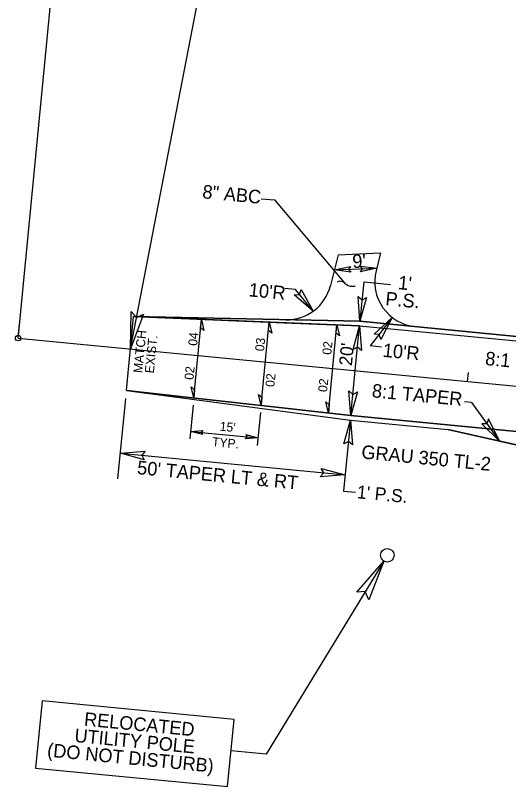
# Model space of a CAD drawing. Extents: x 2061030 to 2061632, y 912568 to 912882.
# Drawn here: x 2061029.7 to 2061138.9, y 912624.1 to 912794.9 of the extents above; entities that cross this region are included whole.
import ezdxf

# ---------------------------------------------------------------- set-up
doc = ezdxf.new("R2010")
doc.units = 0
for name, color, linetype in [('Prop Dimension', 7, 'Continuous'), ('Prop Dimension Text', 7, 'Continuous'), ('Prop EOT', 7, 'Continuous'), ('Prop Guardrail Anchor Unit CELL', 7, 'Continuous'), ('Prop Horizontal Alignment', 7, 'Continuous'), ('Prop Horizontal Alignment Station Label', 7, 'Continuous'), ('Prop Horizontal Alignment Tick Large', 7, 'Continuous'), ('Prop Horizontal Alignment Tick Small', 7, 'Continuous'), ('Prop Lane Lines', 7, 'Continuous'), ('Prop Paved Shoulder', 7, 'Continuous'), ('Prop Shade Light', 7, 'Continuous'), ('Prop Shade Medium', 7, 'Continuous'), ('Prop Superelevation  Arrow CELL', 7, 'Continuous'), ('Prop Superelevation Label', 7, 'Continuous'), ('Prop Terminator CELL', 7, 'Continuous')]:
    doc.layers.add(name, color=color, linetype=linetype)

msp = doc.modelspace()

# ---------------------------------------------------------------- linework, layer by layer
at = {"layer": 'Prop Dimension'}
for p, q in [((2061055.22, 912721.01), (2061080.91, 912854.17)), ((2061084.16, 912754.29), (2061087.18, 912754.01)), ((2061102.92, 912735.37), (2061087.18, 912754.01)), ((2061100.37, 912738.51), (2061109.74, 912738.9)), ((2061091.78, 912734.16), (2061089.43, 912734.38)), ((2061106.88, 912735.86), (2061106.04, 912727.15)), ((2061106.88, 912735.86), (2061112.83, 912735.28)), ((2061095.64, 912729.36), (2061091.78, 912734.16)), ((2061113.19, 912728), (2061108.32, 912721.68)), ((2061104.02, 912706.25), (2061105.95, 912726.15)), ((2061110.83, 912721.44), (2061108.32, 912721.68)), ((2061052.43, 912692.24), (2061054.15, 912710.02)), ((2061130.7, 912709.18), (2061129.21, 912709.33)), ((2061130.7, 912709.18), (2061136.94, 912700.6)), ((2061103.93, 912705.25), (2061102.41, 912689.55)), ((2061052.98, 912697.92), (2061102.75, 912693.11)), ((2061102.41, 912689.55), (2061105.07, 912689.29))]:
    msp.add_line(p, q, dxfattribs=at)
msp.add_open_spline([(2061104.97, 912734.86), (2061103.28, 912734.69), (2061103.11, 912735.58), (2061101.49, 912736.24), (2061100.98, 912735.82)], degree=3, dxfattribs=at)
at = {"layer": 'Prop Dimension Text'}
for p, q in [((2061111.3, 912674.05), (2061085.29, 912631.24)), ((2061085.29, 912631.24), (2061077.48, 912632))]:
    msp.add_line(p, q, dxfattribs=at)
msp.add_lwpolyline([(2061034.19, 912628.21), (2061076.72, 912624.1), (2061078.15, 912638.95), (2061035.63, 912643.06)], close=True, dxfattribs=at)
msp.add_circle((2061112.08, 912675.33), 1.5, dxfattribs=at)
at = {"layer": 'Prop EOT'}
for p, q in [((2061054.33, 912711.84), (2061055.91, 912728.18)), ((2061055.91, 912728.18), (2061089.24, 912726.83)), ((2061105.95, 912726.15), (2061055.91, 912728.18)), ((2061105.95, 912726.15), (2061429.44, 912694.88)), ((2061054.33, 912711.84), (2061104.02, 912706.25)), ((2061104.02, 912706.25), (2061477.28, 912670.17))]:
    msp.add_line(p, q, dxfattribs=at)
at = {"layer": 'Prop Horizontal Alignment'}
msp.add_line((2061030.33, 912723.42), (2061621.2, 912666.3), dxfattribs=at)
at = {"layer": 'Prop Horizontal Alignment Station Label'}
msp.add_line((2061030.39, 912724.01), (2061043.47, 912859.35), dxfattribs=at)
msp.add_circle((2061030.33, 912723.42), 0.6, dxfattribs=at)
at = {"layer": 'Prop Horizontal Alignment Tick Large'}
msp.add_line((2061030.33, 912723.42), (2061030.64, 912726.6), dxfattribs=at)
at = {"layer": 'Prop Horizontal Alignment Tick Small'}
msp.add_line((2061129.87, 912713.8), (2061130.06, 912715.79), dxfattribs=at)
at = {"layer": 'Prop Lane Lines'}
msp.add_line((2061089.24, 912726.83), (2061105.95, 912726.15), dxfattribs=at)
at = {"layer": 'Prop Paved Shoulder'}
for p, q in [((2061101.2, 912741.84), (2061099.51, 912735.06)), ((2061101.2, 912741.84), (2061110.59, 912742.27)), ((2061110.59, 912742.27), (2061109.6, 912738.34)), ((2061055.91, 912728.18), (2061106.04, 912727.15)), ((2061106.04, 912727.15), (2061165.24, 912721.43)), ((2061054.33, 912711.84), (2061103.93, 912705.25)), ((2061103.93, 912705.25), (2061125.49, 912703.17)), ((2061148.44, 912698.02), (2061125.49, 912703.17))]:
    msp.add_line(p, q, dxfattribs=at)
for centre, start, end in [((2061119.3, 912735.91), 165.9729, 264.4787), ((2061089.81, 912737.48), 268.8252, 345.9729)]:
    msp.add_arc(centre, 10, start, end, dxfattribs=at)
at = {"layer": 'Prop Shade Light'}
msp.add_lwpolyline([(2061034.19, 912628.21), (2061076.72, 912624.1), (2061078.15, 912638.95), (2061035.63, 912643.06)], close=True, dxfattribs=at)
at = {"layer": 'Prop Shade Medium'}
for p, q in [((2061106.04, 912727.15), (2061055.91, 912728.18)), ((2061055.91, 912728.18), (2061105.95, 912726.15)), ((2061105.95, 912726.15), (2061229.25, 912714.23)), ((2061165.24, 912721.43), (2061106.04, 912727.15)), ((2061104.02, 912706.25), (2061054.33, 912711.84)), ((2061054.33, 912711.84), (2061103.93, 912705.25)), ((2061103.93, 912705.25), (2061125.49, 912703.17)), ((2061227.33, 912694.33), (2061104.02, 912706.25))]:
    msp.add_line(p, q, dxfattribs=at)
msp.add_lwpolyline([(2061125.49, 912703.17), (2061148.44, 912698.02), (2061148.66, 912700.34), (2061227.17, 912692.75), (2061208.38, 912694.57), (2061227.17, 912692.75)], dxfattribs=at)
at = {"layer": 'Prop Superelevation  Arrow CELL'}
for p, q in [((2061069.24, 912710.16), (2061070.92, 912727.57)), ((2061084.14, 912708.48), (2061085.93, 912726.96)), ((2061099.05, 912706.81), (2061100.94, 912726.36))]:
    msp.add_line(p, q, dxfattribs=at)
for points in [[(2061070.92, 912727.57), (2061071.48, 912725.1), (2061070.74, 912725.73)], [(2061085.93, 912726.96), (2061086.5, 912724.5), (2061085.75, 912725.12)], [(2061100.94, 912726.36), (2061101.51, 912723.89), (2061100.76, 912724.51)], [(2061069.24, 912710.16), (2061068.67, 912712.62), (2061069.41, 912712)], [(2061084.14, 912708.48), (2061083.58, 912710.95), (2061084.32, 912710.32)], [(2061099.05, 912706.81), (2061098.49, 912709.27), (2061099.23, 912708.65)]]:
    msp.add_lwpolyline(points, close=True, dxfattribs=at)
at = {"layer": 'Prop Superelevation Label'}
for p, q in [((2061069.08, 912708.58), (2061068.36, 912701.12)), ((2061084, 912706.96), (2061083.29, 912699.67)), ((2061068.52, 912702.76), (2061083.45, 912701.32))]:
    msp.add_line(p, q, dxfattribs=at)
at = {"layer": 'Prop Terminator CELL'}
for points in [[(2061103.99, 912738.04), (2061100.37, 912738.51), (2061103.96, 912739.3), (2061103.53, 912738.64)], [(2061106.12, 912739.37), (2061109.74, 912738.9), (2061106.15, 912738.11), (2061106.59, 912738.77)], [(2061092.98, 912734.15), (2061095.64, 912729.36), (2061091.49, 912732.99), (2061092.67, 912733.06)], [(2061107.49, 912732.43), (2061106.04, 912727.15), (2061105.61, 912732.65), (2061106.5, 912731.87)], [(2061058.12, 912728.7), (2061055.22, 912721.01), (2061055.34, 912729.28), (2061056.56, 912727.99)], [(2061109.16, 912724.29), (2061113.19, 912728), (2061110.64, 912723.11), (2061110.3, 912724.25)], [(2061104.5, 912720.87), (2061105.95, 912726.15), (2061106.38, 912720.66), (2061105.49, 912721.44)], [(2061105.47, 912711.53), (2061104.02, 912706.25), (2061103.59, 912711.74), (2061104.48, 912710.96)], [(2061102.48, 912699.97), (2061103.93, 912705.25), (2061104.36, 912699.75), (2061103.47, 912700.53)], [(2061133.02, 912704.42), (2061136.94, 912700.6), (2061134.53, 912705.55), (2061134.16, 912704.43)], [(2061071.16, 912702.04), (2061068.52, 912702.76), (2061071.27, 912702.98), (2061070.88, 912702.53)], [(2061080.81, 912702.04), (2061083.45, 912701.32), (2061080.7, 912701.1), (2061081.09, 912701.54)], [(2061058.27, 912696.47), (2061052.98, 912697.92), (2061058.48, 912698.35), (2061057.7, 912697.46)], [(2061097.47, 912694.55), (2061102.75, 912693.11), (2061097.25, 912692.67), (2061098.03, 912693.56)], [(2061105.31, 912667.16), (2061111.3, 912674.05), (2061107.97, 912665.48), (2061107.2, 912667.29)]]:
    msp.add_lwpolyline(points, close=True, dxfattribs=at)

# ---------------------------------------------------------------- texts
at = {"layer": 'Prop Dimension Text'}
for s, height, rotation, p in [('8" ABC', 3, 354.4787, (2061071.04, 912754.41)), ("9'", 3, 2.9377, (2061104.42, 912738.91)), ("1'", 3, 354.4787, (2061114.38, 912734.27)), ("10'R", 3, 354.4787, (2061081.32, 912732.68)), ('P.S.', 3, 354.4787, (2061111.57, 912730.72)), ('MATCH', 2, 84.4787, (2061057.83, 912715.62)), ('EXIST.', 2, 84.4787, (2061060.37, 912715.56)), ("20'", 2.88, 84.4787, (2061104.24, 912717.2)), ("10'R", 3, 354.4787, (2061110.99, 912719.29)), ('8:1 TAPER', 3, 354.4787, (2061133.67, 912717.47)), ('8:1 TAPER', 3, 354.4787, (2061108.58, 912710.33)), ("50' TAPER LT & RT", 3, 354.4787, (2061056.59, 912693.32)), ("1' P.S.", 2.88, 354.4787, (2061105.26, 912687.97)), ('RELOCATED', 3, 354.4787, (2061044.84, 912637.6)), ('UTILITY POLE', 3, 354.4787, (2061042.71, 912633.99)), ('(DO NOT DISTURB)', 3, 354.4787, (2061036.67, 912630.75))]:
    msp.add_text(s, height=height, rotation=rotation, dxfattribs=at).set_placement(p)
at = {"layer": 'Prop Guardrail Anchor Unit CELL'}
msp.add_text('GRAU 350 TL-2', height=3, rotation=354.4787, dxfattribs=at).set_placement((2061106.25, 912696.78))
at = {"layer": 'Prop Superelevation Label'}
for s, rotation, p in [('04', 84.4787, (2061069.97, 912721.65)), ('03', 84.4787, (2061084.78, 912720.43)), ('02', 84.4787, (2061099.68, 912719.66)), ('02', 84.4787, (2061069.15, 912714.12)), ('02', 84.4787, (2061087.07, 912712.54)), ('02', 84.4787, (2061098.75, 912711.4)), ("15'", 354.4787, (2061074.91, 912702.93)), ('TYP.', 354.4787, (2061073.21, 912699.51))]:
    msp.add_text(s, height=2, rotation=rotation, dxfattribs=at).set_placement(p)

doc.saveas('drawing.dxf')
